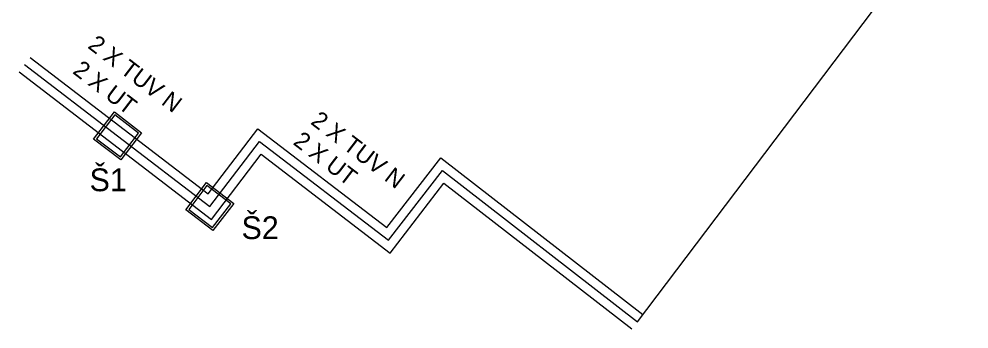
# Model space of a CAD drawing. Extents: x -606118 to -604472, y -1157869 to -1156854.
# Drawn here: x -604883.4 to -604799.9, y -1157493.3 to -1157466.1 of the extents above; entities that cross this region are included whole.
import ezdxf

# ---------------------------------------------------------------- set-up
doc = ezdxf.new("R2010")
doc.units = 0
for name, color, linetype in [('Osa trasy teplovodu', 7, 'Continuous'), ('označení šachty', 7, 'Continuous'), ('Teplovod - trasa - okraj', 7, 'Continuous'), ('Teplovod - trasa popis', 7, 'Continuous'), ('Teplovod - trasa popis 2', 7, 'Continuous'), ('Šachta trasy teplovodu', 7, 'Continuous')]:
    doc.layers.add(name, color=color, linetype=linetype)

msp = doc.modelspace()

# ---------------------------------------------------------------- linework, layer by layer
at = {"layer": 'Osa trasy teplovodu'}
msp.add_line((-604829.051, -1157492.681), (-604799.906, -1157454.179), dxfattribs=at)
msp.add_lwpolyline([(-604882.923, -1157470.107), (-604874.745, -1157476.369), (-604866.646, -1157482.569), (-604862.269, -1157476.852), (-604850.941, -1157485.524), (-604846.197, -1157479.4), (-604829.051, -1157492.681)], dxfattribs=at)
at = {"layer": 'Teplovod - trasa - okraj'}
for points in [[(-604882.437, -1157469.472), (-604866.795, -1157481.447), (-604862.418, -1157475.73), (-604851.086, -1157484.405), (-604846.34, -1157478.278), (-604828.561, -1157492.049)], [(-604883.409, -1157470.742), (-604866.497, -1157483.691), (-604862.12, -1157477.974), (-604850.796, -1157486.643), (-604846.054, -1157480.522), (-604829.541, -1157493.313)]]:
    msp.add_lwpolyline(points, dxfattribs=at)
at = {"layer": 'Šachta trasy teplovodu'}
for points in [[(-604876.85, -1157476.647), (-604875.023, -1157474.26), (-604872.636, -1157476.086), (-604874.463, -1157478.474), (-604876.85, -1157476.647)], [(-604874.498, -1157478.21), (-604872.9, -1157476.121), (-604874.988, -1157474.523), (-604876.587, -1157476.612), (-604874.498, -1157478.21)], [(-604868.751, -1157482.847), (-604866.924, -1157480.46), (-604864.537, -1157482.286), (-604866.364, -1157484.674), (-604868.751, -1157482.847)], [(-604866.399, -1157484.41), (-604864.801, -1157482.321), (-604866.889, -1157480.723), (-604868.488, -1157482.812), (-604866.399, -1157484.41)]]:
    msp.add_lwpolyline(points, dxfattribs=at)

# ---------------------------------------------------------------- texts
at = {"layer": 'označení šachty'}
for s, p in [('Š1', (-604877.206, -1157481.218)), ('Š2', (-604863.851, -1157485.422))]:
    msp.add_text(s, height=2, dxfattribs=at).set_placement(p)
at = {"layer": 'Teplovod - trasa popis'}
for rotation, p in [(322.57525, (-604878.771, -1157470.809)), (322.57524, (-604859.396, -1157477.043))]:
    msp.add_text('2 X UT', height=1.5, rotation=rotation, dxfattribs=at).set_placement(p)
at = {"layer": 'Teplovod - trasa popis 2'}
for p in [(-604877.445, -1157468.582), (-604857.853, -1157475.255)]:
    msp.add_text('2 X TUV N', height=1.5, rotation=322.57525, dxfattribs=at).set_placement(p)

doc.saveas('drawing.dxf')
